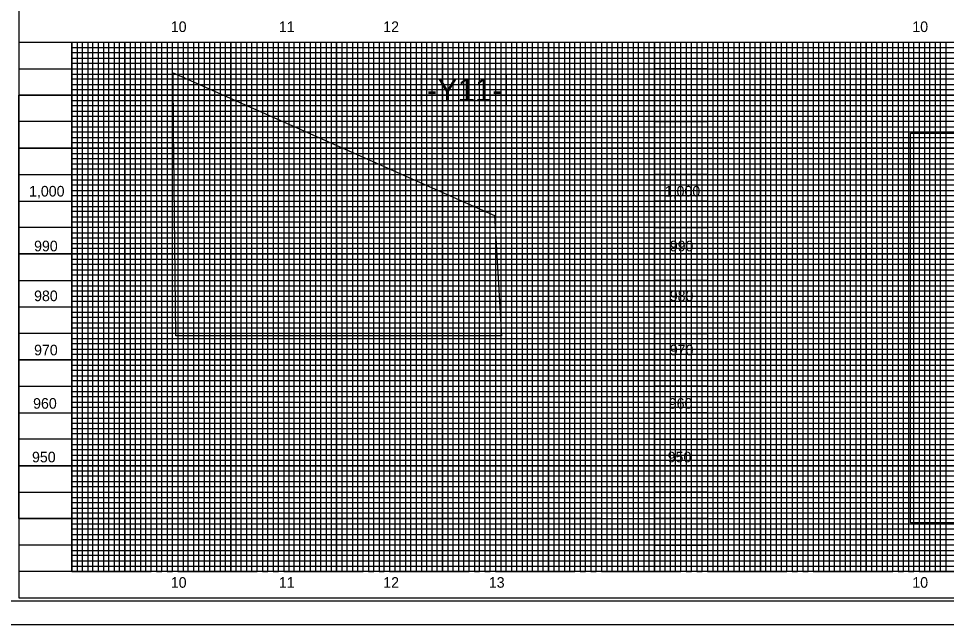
# Model space of a CAD drawing. Extents: x 1628636 to 1631253, y 896159 to 897520.
# Drawn here: x 1629226 to 1630102, y 896159 to 896731 of the extents above; entities that cross this region are included whole.
import ezdxf

# ---------------------------------------------------------------- set-up
doc = ezdxf.new("R2010")
doc.units = 0
for name, color, linetype in [('Prop DSN Text', 7, 'Continuous'), ('Prop PHM Black Shape', 7, 'Continuous'), ('Scratch_Level_6', 7, 'Continuous'), ('Sheet Cutting Line CELL', 7, 'Continuous'), ('Sheet DOT Grid CELL', 7, 'Continuous'), ('Sheet Layout Profile Border Port 2', 7, 'Continuous'), ('Sheet Plot Border Inside CELL', 7, 'Continuous'), ('Sheet Plot Border Outside CELL', 7, 'Continuous'), ('Sheet Profile CELL', 7, 'Continuous'), ('Sheet Profile Grid Major CELL', 7, 'Continuous'), ('Sheet Profile Grid Middle CELL', 7, 'Continuous'), ('Sheet Profile Grid Minor CELL', 7, 'Continuous')]:
    doc.layers.add(name, color=color, linetype=linetype)

msp = doc.modelspace()

# ---------------------------------------------------------------- linework, layer by layer
at = {"layer": 'Prop PHM Black Shape'}
for points in [[(1629826.5, 896708.9), (1629876.5, 896708.9), (1629876.5, 896683.9), (1629826.5, 896683.9)], [(1629826.5, 896683.9), (1629876.5, 896683.9), (1629876.5, 896658.9), (1629826.5, 896658.9)], [(1629606.5, 896678.9), (1629686.5, 896678.9), (1629686.5, 896648.9), (1629606.5, 896648.9)], [(1629826.5, 896658.9), (1629876.5, 896658.9), (1629876.5, 896633.9), (1629826.5, 896633.9)], [(1629826.5, 896633.9), (1629876.5, 896633.9), (1629876.5, 896608.9), (1629826.5, 896608.9)], [(1629826.5, 896608.9), (1629876.5, 896608.9), (1629876.5, 896583.9), (1629826.5, 896583.9)], [(1629826.5, 896583.9), (1629876.5, 896583.9), (1629876.5, 896558.9), (1629826.5, 896558.9)], [(1629826.5, 896558.9), (1629876.5, 896558.9), (1629876.5, 896533.9), (1629826.5, 896533.9)], [(1629826.5, 896533.9), (1629876.5, 896533.9), (1629876.5, 896508.9), (1629826.5, 896508.9)], [(1629826.5, 896508.9), (1629876.5, 896508.9), (1629876.5, 896483.9), (1629826.5, 896483.9)], [(1629826.5, 896483.9), (1629876.5, 896483.9), (1629876.5, 896458.9), (1629826.5, 896458.9)], [(1629826.5, 896458.9), (1629876.5, 896458.9), (1629876.5, 896433.9), (1629826.5, 896433.9)], [(1629826.5, 896433.9), (1629876.5, 896433.9), (1629876.5, 896408.9), (1629826.5, 896408.9)], [(1629826.5, 896408.9), (1629876.5, 896408.9), (1629876.5, 896383.9), (1629826.5, 896383.9)], [(1629826.5, 896383.9), (1629876.5, 896383.9), (1629876.5, 896358.9), (1629826.5, 896358.9)], [(1629826.5, 896358.9), (1629876.5, 896358.9), (1629876.5, 896333.9), (1629826.5, 896333.9)], [(1629826.5, 896333.9), (1629876.5, 896333.9), (1629876.5, 896308.9), (1629826.5, 896308.9)], [(1629826.5, 896308.9), (1629876.5, 896308.9), (1629876.5, 896283.9), (1629826.5, 896283.9)], [(1629826.5, 896283.9), (1629876.5, 896283.9), (1629876.5, 896258.9), (1629826.5, 896258.9)], [(1629826.5, 896258.9), (1629876.5, 896258.9), (1629876.5, 896233.9), (1629826.5, 896233.9)], [(1629826.5, 896233.9), (1629876.5, 896233.9), (1629876.5, 896208.9), (1629826.5, 896208.9)]]:
    msp.add_lwpolyline(points, close=True, dxfattribs=at)
at = {"layer": 'Scratch_Level_6'}
for points in [[(1629372.8, 896602.66), (1629372.5, 896622.96), (1629372.09, 896679.94), (1629675.45, 896545.33), (1629682.06, 896431.71), (1629374.8, 896431.63)], [(1629226.5, 896658.9), (1629776.5, 896658.9), (1629776.5, 896258.9), (1629226.5, 896258.9)], [(1630068.19, 896623), (1630370.03, 896623), (1630370.03, 896254.89), (1630068.19, 896254.89)]]:
    msp.add_lwpolyline(points, close=True, dxfattribs=at)
at = {"layer": 'Sheet Cutting Line CELL'}
msp.add_line((1629059.5, 896158.9), (1630743.5, 896158.9), dxfattribs=at)
at = {"layer": 'Sheet DOT Grid CELL'}
for p, q in [((1629226.5, 896708.9), (1630726.39, 896708.9)), ((1629276.5, 896708.9), (1629276.5, 896208.9)), ((1629326.5, 896708.9), (1629326.5, 896208.9)), ((1629376.5, 896708.9), (1629376.5, 896208.9)), ((1629426.5, 896708.9), (1629426.5, 896208.9)), ((1629476.5, 896708.9), (1629476.5, 896208.9)), ((1629526.5, 896708.9), (1629526.5, 896208.9)), ((1629576.5, 896708.9), (1629576.5, 896208.9)), ((1629626.5, 896708.9), (1629626.5, 896208.9)), ((1629676.5, 896708.9), (1629676.5, 896208.9)), ((1629726.5, 896708.9), (1629726.5, 896208.9)), ((1629776.5, 896708.9), (1629776.5, 896208.9)), ((1629826.5, 896708.9), (1629826.5, 896208.9)), ((1629876.5, 896708.9), (1629876.5, 896208.9)), ((1629926.5, 896708.9), (1629926.5, 896208.9)), ((1629976.5, 896708.9), (1629976.5, 896208.9)), ((1630026.5, 896708.9), (1630026.5, 896208.9)), ((1630076.5, 896708.9), (1630076.5, 896208.9)), ((1629226.5, 896658.9), (1630726.39, 896658.9)), ((1629226.5, 896608.9), (1630726.39, 896608.9)), ((1629226.5, 896558.9), (1630726.39, 896558.9)), ((1629226.5, 896508.9), (1630726.39, 896508.9)), ((1629226.5, 896458.9), (1630726.39, 896458.9)), ((1629226.5, 896408.9), (1630726.39, 896408.9)), ((1629226.5, 896358.9), (1630726.39, 896358.9)), ((1629226.5, 896308.9), (1630726.39, 896308.9)), ((1629226.5, 896258.9), (1630726.39, 896258.9))]:
    msp.add_line(p, q, dxfattribs=at)
at = {"layer": 'Sheet Layout Profile Border Port 2'}
msp.add_lwpolyline([(1629276.5, 896708.9), (1630676.5, 896708.9), (1630676.5, 896208.9), (1629276.5, 896208.9)], close=True, dxfattribs=at)
at = {"layer": 'Sheet Plot Border Inside CELL'}
msp.add_lwpolyline([(1629072.5, 896181.35), (1630739, 896181.35), (1630739, 897236.45), (1629072.5, 897236.45)], close=True, dxfattribs=at)
at = {"layer": 'Sheet Plot Border Outside CELL'}
msp.add_lwpolyline([(1629059.5, 896158.9), (1630743.5, 896158.9), (1630743.5, 897258.9), (1629059.5, 897258.9)], close=True, dxfattribs=at)
at = {"layer": 'Sheet Profile CELL'}
for p, q in [((1629226.5, 896708.9), (1630726.5, 896708.9)), ((1630726.5, 896208.9), (1629226.5, 896208.9)), ((1629226.5, 896183.9), (1630726.5, 896183.9)), ((1629226.5, 896183.9), (1629226.5, 896183.9)), ((1629226.5, 896183.9), (1629226.5, 896183.9)), ((1629226.5, 896183.9), (1629226.5, 896183.9)), ((1629226.5, 896183.9), (1629226.5, 896183.9)), ((1629226.5, 896183.9), (1629226.5, 896183.9)), ((1629226.5, 896183.9), (1629226.5, 896183.9)), ((1629226.5, 896183.9), (1629226.5, 896183.9))]:
    msp.add_line(p, q, dxfattribs=at)
msp.add_lwpolyline([(1630726.5, 897233.9), (1629226.5, 897233.9), (1629226.5, 896183.9), (1630726.5, 896183.9)], close=True, dxfattribs=at)
msp.add_lwpolyline([(1629264, 896183.9), (1629264, 896183.9)], dxfattribs=at)
at = {"layer": 'Sheet Profile Grid Major CELL'}
for p, q in [((1629726.5, 896708.9), (1629776.5, 896708.9)), ((1629826.5, 896708.9), (1629876.5, 896708.9)), ((1629926.5, 896708.9), (1629976.5, 896708.9)), ((1630026.5, 896708.9), (1630076.5, 896708.9)), ((1629826.5, 896683.9), (1629876.5, 896683.9)), ((1629876.5, 896658.9), (1629826.5, 896658.9)), ((1629826.5, 896633.9), (1629876.5, 896633.9)), ((1629826.5, 896608.9), (1629876.5, 896608.9)), ((1629826.5, 896583.9), (1629876.5, 896583.9)), ((1629826.5, 896558.9), (1629876.5, 896558.9)), ((1629826.5, 896533.9), (1629876.5, 896533.9)), ((1629876.5, 896508.9), (1629826.5, 896508.9)), ((1629826.5, 896483.9), (1629876.5, 896483.9)), ((1629826.5, 896458.9), (1629876.5, 896458.9)), ((1629826.5, 896433.9), (1629876.5, 896433.9)), ((1629876.5, 896408.9), (1629826.5, 896408.9)), ((1629826.5, 896383.9), (1629876.5, 896383.9)), ((1629876.5, 896358.9), (1629826.5, 896358.9)), ((1629826.5, 896333.9), (1629876.5, 896333.9)), ((1629826.5, 896308.9), (1629876.5, 896308.9)), ((1629826.5, 896283.9), (1629876.5, 896283.9)), ((1629826.5, 896258.9), (1629876.5, 896258.9)), ((1629826.5, 896233.9), (1629876.5, 896233.9)), ((1629226.5, 896208.9), (1629226.5, 896208.9))]:
    msp.add_line(p, q, dxfattribs=at)
for points in [[(1629276.5, 896708.9), (1629276.5, 896208.9), (1629326.5, 896208.9), (1629326.5, 896708.9), (1629376.5, 896708.9), (1629376.5, 896208.9), (1629426.5, 896208.9), (1629426.5, 896708.9), (1629476.5, 896708.9), (1629476.5, 896208.9), (1629526.5, 896208.9), (1629526.5, 896708.9), (1629576.5, 896708.9), (1629576.5, 896208.9), (1629626.5, 896208.9), (1629626.5, 896708.9), (1629676.5, 896708.9), (1629676.5, 896208.9), (1629726.5, 896208.9), (1629726.5, 896708.9), (1629776.5, 896708.9), (1629776.5, 896208.9), (1629826.5, 896208.9), (1629826.5, 896708.9), (1629876.5, 896708.9), (1629876.5, 896208.9), (1629926.5, 896208.9), (1629926.5, 896708.9), (1629976.5, 896708.9), (1629976.5, 896208.9), (1630026.5, 896208.9), (1630026.5, 896708.9), (1630076.5, 896708.9), (1630076.5, 896208.9), (1630126.5, 896208.9)], [(1630726.5, 896658.9), (1629226.5, 896658.9)], [(1630726.5, 896608.9), (1629226.5, 896608.9), (1629226.5, 896558.9), (1630726.5, 896558.9)], [(1630726.5, 896508.9), (1629226.5, 896508.9), (1629226.5, 896458.9), (1630726.5, 896458.9)], [(1630726.5, 896408.9), (1629226.5, 896408.9), (1629226.5, 896358.9), (1630726.5, 896358.9)], [(1630726.5, 896308.9), (1629226.5, 896308.9), (1629226.5, 896308.9), (1629226.5, 896258.9), (1630726.5, 896258.9)], [(1630726.5, 896208.9), (1629226.5, 896208.9)]]:
    msp.add_lwpolyline(points, dxfattribs=at)
at = {"layer": 'Sheet Profile Grid Middle CELL'}
for points in [[(1629251.5, 896708.9), (1629301.5, 896708.9), (1629301.5, 896208.9), (1629351.5, 896208.9), (1629351.5, 896708.9), (1629401.5, 896708.9), (1629401.5, 896208.9), (1629451.5, 896208.9), (1629451.5, 896708.9), (1629501.5, 896708.9), (1629501.5, 896208.9), (1629551.5, 896208.9), (1629551.5, 896708.9), (1629601.5, 896708.9), (1629601.5, 896208.9), (1629651.5, 896208.9), (1629651.5, 896708.9), (1629701.5, 896708.9), (1629701.5, 896208.9), (1629751.5, 896208.9), (1629751.5, 896708.9), (1629801.5, 896708.9), (1629801.5, 896208.9), (1629851.5, 896208.9), (1629851.5, 896208.9), (1629851.5, 896708.9), (1629901.5, 896708.9), (1629901.5, 896208.9), (1629951.5, 896208.9), (1629951.5, 896708.9), (1630001.5, 896708.9), (1630001.5, 896208.9), (1630051.5, 896208.9), (1630051.5, 896708.9), (1630101.5, 896708.9), (1630101.5, 896208.9), (1630151.5, 896208.9)], [(1629226.5, 896683.9), (1630726.5, 896683.9)], [(1630726.5, 896633.9), (1629226.5, 896633.9), (1629226.5, 896583.9), (1630726.5, 896583.9)], [(1630726.5, 896533.9), (1629226.5, 896533.9), (1629226.5, 896483.9), (1630726.5, 896483.9)], [(1630726.5, 896433.9), (1629226.5, 896433.9), (1629226.5, 896383.9), (1630726.5, 896383.9)], [(1630726.5, 896333.9), (1629226.5, 896333.9), (1629226.5, 896283.9), (1630726.5, 896283.9)], [(1630726.5, 896233.9), (1629226.5, 896233.9)]]:
    msp.add_lwpolyline(points, dxfattribs=at)
at = {"layer": 'Sheet Profile Grid Minor CELL'}
for p, q in [((1629276.5, 896703.9), (1630676.5, 896703.9)), ((1630676.5, 896698.9), (1629276.5, 896698.9)), ((1629276.5, 896693.9), (1630676.5, 896693.9)), ((1630676.5, 896688.9), (1629276.5, 896688.9)), ((1629276.5, 896678.9), (1630676.5, 896678.9)), ((1630676.5, 896673.9), (1629276.5, 896673.9)), ((1629276.5, 896668.9), (1630676.5, 896668.9)), ((1630676.5, 896663.9), (1629276.5, 896663.9)), ((1629276.5, 896653.9), (1630676.5, 896653.9)), ((1630676.5, 896648.9), (1629276.5, 896648.9)), ((1629276.5, 896643.9), (1630676.5, 896643.9)), ((1630676.5, 896638.9), (1629276.5, 896638.9)), ((1629276.5, 896628.9), (1630676.5, 896628.9)), ((1630676.5, 896623.9), (1629276.5, 896623.9)), ((1629276.5, 896618.9), (1630676.5, 896618.9)), ((1630676.5, 896613.9), (1629276.5, 896613.9)), ((1629276.5, 896603.9), (1630676.5, 896603.9)), ((1630676.5, 896598.9), (1629276.5, 896598.9)), ((1629276.5, 896593.9), (1630676.5, 896593.9)), ((1630676.5, 896588.9), (1629276.5, 896588.9)), ((1629276.5, 896578.9), (1630676.5, 896578.9)), ((1630676.5, 896573.9), (1629276.5, 896573.9)), ((1629276.5, 896568.9), (1630676.5, 896568.9)), ((1630676.5, 896563.9), (1629276.5, 896563.9)), ((1629276.5, 896553.9), (1630676.5, 896553.9)), ((1630676.5, 896548.9), (1629276.5, 896548.9)), ((1629276.5, 896543.9), (1630676.5, 896543.9)), ((1630676.5, 896538.9), (1629276.5, 896538.9)), ((1629276.5, 896528.9), (1630676.5, 896528.9)), ((1630676.5, 896523.9), (1629276.5, 896523.9)), ((1629276.5, 896518.9), (1630676.5, 896518.9)), ((1630676.5, 896513.9), (1629276.5, 896514.05)), ((1629276.5, 896503.9), (1630676.5, 896503.9)), ((1630676.5, 896498.9), (1629276.5, 896498.9)), ((1629276.5, 896493.9), (1630676.5, 896493.9)), ((1630676.5, 896488.9), (1629276.5, 896488.9)), ((1629276.5, 896478.9), (1630676.5, 896478.9)), ((1630676.5, 896473.9), (1629276.5, 896473.9)), ((1629276.5, 896468.9), (1630676.5, 896468.9)), ((1630676.5, 896463.9), (1629276.5, 896463.9)), ((1629276.5, 896453.9), (1630676.5, 896453.9)), ((1630676.5, 896448.9), (1629276.5, 896448.9)), ((1629276.5, 896443.9), (1630676.5, 896443.9)), ((1630676.5, 896438.9), (1629276.5, 896438.9)), ((1629276.5, 896428.9), (1630676.5, 896428.9)), ((1630676.5, 896423.9), (1629276.5, 896423.9)), ((1629276.5, 896418.9), (1630676.5, 896418.9)), ((1630676.5, 896413.9), (1629276.5, 896413.9)), ((1629276.5, 896403.9), (1630676.5, 896403.9)), ((1630676.5, 896398.9), (1629276.5, 896398.9)), ((1629276.5, 896393.9), (1630676.5, 896393.9)), ((1630676.5, 896388.9), (1629276.5, 896388.9)), ((1629276.5, 896378.9), (1630676.5, 896378.9)), ((1630676.5, 896373.9), (1629276.5, 896373.9)), ((1629276.5, 896368.9), (1630676.5, 896368.9)), ((1630676.5, 896363.9), (1629276.5, 896363.9)), ((1629276.5, 896353.9), (1630676.5, 896353.9)), ((1630676.5, 896348.9), (1629276.5, 896348.9)), ((1629276.5, 896343.9), (1630676.5, 896343.9)), ((1630676.5, 896338.9), (1629276.5, 896338.9)), ((1629276.5, 896328.9), (1630676.5, 896328.9)), ((1630676.5, 896323.9), (1629276.5, 896323.9)), ((1629276.5, 896318.9), (1630676.5, 896318.9)), ((1630676.5, 896313.9), (1629276.5, 896313.9)), ((1629276.5, 896303.9), (1630676.5, 896303.9)), ((1630676.5, 896298.9), (1629276.5, 896298.9)), ((1629276.5, 896293.9), (1630676.5, 896293.9)), ((1630676.5, 896288.9), (1629276.5, 896288.9)), ((1629276.5, 896278.9), (1630676.5, 896278.9)), ((1630676.5, 896273.9), (1629276.5, 896273.9)), ((1629276.5, 896268.9), (1630676.5, 896268.9)), ((1630676.5, 896263.9), (1629276.5, 896263.9)), ((1629276.5, 896253.9), (1630676.5, 896253.9)), ((1630676.5, 896248.9), (1629276.5, 896248.9)), ((1629276.5, 896243.9), (1630676.5, 896243.9)), ((1630676.5, 896238.9), (1629276.5, 896238.9)), ((1629276.5, 896228.9), (1630676.5, 896228.9)), ((1630676.5, 896223.9), (1629276.5, 896223.9)), ((1629276.5, 896218.9), (1630676.5, 896218.9)), ((1629276.5, 896213.9), (1630676.5, 896213.9))]:
    msp.add_line(p, q, dxfattribs=at)
for points in [[(1629276.5, 896708.9), (1629281.5, 896708.9), (1629281.5, 896208.9), (1629286.5, 896208.9), (1629286.5, 896708.9), (1629291.5, 896708.9), (1629291.5, 896208.9), (1629296.5, 896208.9), (1629296.5, 896708.9), (1629306.5, 896708.9), (1629306.5, 896208.9), (1629311.5, 896208.9), (1629311.5, 896708.9), (1629316.5, 896708.9), (1629316.5, 896208.9), (1629321.5, 896208.9), (1629331.5, 896208.9), (1629336.5, 896208.9), (1629336.5, 896708.9), (1629341.5, 896708.9), (1629341.5, 896208.9), (1629346.5, 896208.9), (1629346.5, 896708.9), (1629356.5, 896708.9), (1629356.5, 896208.9), (1629361.5, 896208.9), (1629361.5, 896708.9), (1629366.5, 896708.9), (1629366.5, 896208.9), (1629371.5, 896208.9), (1629371.5, 896708.9), (1629381.5, 896708.9), (1629381.5, 896208.9), (1629386.5, 896208.9), (1629386.5, 896708.9), (1629391.5, 896708.9), (1629391.5, 896208.9), (1629396.5, 896208.9), (1629396.5, 896708.9), (1629406.5, 896708.9), (1629406.5, 896208.9), (1629411.5, 896208.9), (1629411.5, 896708.9), (1629416.5, 896708.9), (1629416.5, 896208.9), (1629421.5, 896208.9), (1629421.5, 896708.9), (1629431.5, 896708.9), (1629431.5, 896208.9), (1629436.5, 896208.9), (1629436.5, 896708.9), (1629441.5, 896708.9), (1629441.5, 896208.9), (1629446.5, 896208.9), (1629446.5, 896708.9), (1629456.5, 896708.9), (1629456.5, 896208.9), (1629461.5, 896208.9), (1629461.5, 896708.9), (1629466.5, 896708.9), (1629466.5, 896208.9), (1629471.5, 896208.9), (1629471.5, 896708.9), (1629481.5, 896708.9), (1629481.5, 896208.9), (1629486.5, 896208.9), (1629486.5, 896708.9), (1629491.5, 896708.9), (1629491.5, 896208.9)], [(1629321.5, 896208.9), (1629321.5, 896708.9), (1629331.5, 896708.9), (1629331.5, 896208.9)], [(1629491.5, 896208.9), (1629496.5, 896208.9), (1629496.5, 896708.9), (1629506.5, 896708.9), (1629506.5, 896208.9), (1629511.5, 896208.9), (1629511.5, 896708.9), (1629516.5, 896708.9), (1629516.5, 896208.9), (1629521.5, 896208.9), (1629521.5, 896708.9), (1629531.5, 896708.9), (1629531.5, 896208.9), (1629536.5, 896208.9), (1629536.5, 896708.9), (1629541.5, 896708.9), (1629541.5, 896208.9), (1629546.5, 896208.9), (1629546.5, 896708.9), (1629556.5, 896708.9), (1629556.5, 896208.9), (1629561.5, 896208.9), (1629561.5, 896708.9), (1629566.5, 896708.9), (1629566.5, 896208.9), (1629571.5, 896208.9), (1629571.5, 896708.9), (1629581.5, 896708.9), (1629581.5, 896208.9), (1629586.5, 896208.9), (1629586.5, 896708.9), (1629591.5, 896708.9), (1629591.5, 896208.9), (1629596.5, 896208.9), (1629596.5, 896708.9), (1629606.5, 896708.9), (1629606.5, 896208.9), (1629611.5, 896208.9), (1629611.5, 896708.9), (1629616.5, 896708.9), (1629616.5, 896208.9), (1629621.5, 896208.9), (1629621.5, 896708.9), (1629631.5, 896708.9), (1629631.5, 896208.9), (1629636.5, 896208.9), (1629636.5, 896708.9), (1629641.5, 896708.9), (1629641.5, 896208.9), (1629646.5, 896208.9), (1629646.5, 896708.9), (1629656.5, 896708.9), (1629656.5, 896208.9), (1629661.5, 896208.9), (1629661.5, 896708.9), (1629666.5, 896708.9), (1629666.5, 896208.9), (1629671.5, 896208.9), (1629671.5, 896708.9), (1629681.5, 896708.9), (1629681.5, 896208.9), (1629686.5, 896208.9), (1629686.5, 896708.9), (1629691.5, 896708.9), (1629691.5, 896208.9), (1629696.5, 896208.9), (1629696.5, 896708.9), (1629706.5, 896708.9), (1629706.5, 896208.9), (1629711.5, 896208.9), (1629711.5, 896708.9), (1629716.5, 896708.9), (1629716.5, 896208.9), (1629721.5, 896208.9), (1629721.5, 896708.9), (1629731.5, 896708.9), (1629731.5, 896208.9), (1629736.5, 896208.9), (1629736.5, 896708.9), (1629741.5, 896708.9), (1629741.5, 896208.9), (1629746.5, 896208.9), (1629746.5, 896708.9), (1629756.5, 896708.9), (1629756.5, 896208.9), (1629761.5, 896208.9), (1629761.5, 896708.9), (1629766.5, 896708.9), (1629766.5, 896208.9), (1629771.5, 896208.9), (1629771.5, 896708.9), (1629781.5, 896708.9), (1629781.5, 896208.9), (1629786.5, 896208.9), (1629786.5, 896708.9), (1629791.5, 896708.9), (1629791.5, 896208.9), (1629796.5, 896208.9), (1629796.5, 896708.9), (1629806.5, 896708.9)], [(1629806.5, 896708.9), (1629806.5, 896208.9), (1629811.5, 896208.9), (1629811.5, 896708.9), (1629816.5, 896708.9), (1629816.5, 896208.9), (1629821.5, 896208.9), (1629821.5, 896708.9), (1629831.5, 896708.9), (1629831.5, 896208.9), (1629836.5, 896208.9), (1629836.5, 896708.9), (1629841.5, 896708.9), (1629841.5, 896208.9), (1629846.5, 896208.9), (1629846.5, 896708.9), (1629856.5, 896708.9), (1629856.5, 896208.9), (1629861.5, 896208.9), (1629861.5, 896708.9), (1629866.5, 896708.9), (1629866.5, 896208.9), (1629871.5, 896208.9), (1629871.5, 896708.9), (1629881.5, 896708.9), (1629881.5, 896208.9), (1629886.5, 896208.9), (1629886.5, 896708.9), (1629891.5, 896708.9), (1629891.5, 896208.9), (1629896.5, 896208.9), (1629896.5, 896708.9), (1629906.5, 896708.9), (1629906.5, 896208.9), (1629911.5, 896208.9), (1629911.5, 896708.9), (1629916.5, 896708.9), (1629916.5, 896208.9), (1629921.5, 896208.9), (1629921.5, 896708.9), (1629931.5, 896708.9), (1629931.5, 896208.9), (1629931.5, 896208.9), (1629936.5, 896208.9), (1629936.5, 896708.9), (1629941.5, 896708.9), (1629941.5, 896208.9), (1629946.5, 896208.9), (1629946.5, 896708.9), (1629956.5, 896708.9), (1629956.5, 896208.9), (1629961.5, 896208.9), (1629961.5, 896708.9), (1629966.5, 896708.9), (1629966.5, 896208.9), (1629971.5, 896208.9), (1629971.5, 896708.9), (1629981.5, 896708.9), (1629981.5, 896208.9), (1629986.5, 896208.9), (1629986.5, 896708.9), (1629991.5, 896708.9), (1629991.5, 896208.9), (1629996.5, 896208.9), (1629996.5, 896708.9), (1630006.5, 896708.9), (1630006.5, 896208.9), (1630011.5, 896208.9), (1630011.5, 896708.9), (1630016.5, 896708.9), (1630016.5, 896208.9), (1630021.5, 896208.9), (1630021.5, 896708.9), (1630031.5, 896708.9), (1630031.5, 896208.9), (1630036.5, 896208.9), (1630036.5, 896708.9), (1630041.5, 896708.9), (1630041.5, 896208.9), (1630046.5, 896208.9), (1630046.5, 896708.9), (1630056.5, 896708.9), (1630056.5, 896208.9), (1630061.5, 896208.9), (1630061.5, 896708.9), (1630066.5, 896708.9), (1630066.5, 896208.9), (1630071.5, 896208.9), (1630071.5, 896708.9), (1630081.5, 896708.9), (1630081.5, 896208.9), (1630086.2, 896209.45), (1630086.5, 896208.9), (1630086.5, 896708.9), (1630091.5, 896708.9), (1630091.5, 896208.9), (1630096.5, 896208.9), (1630096.5, 896708.9), (1630106.5, 896708.9)]]:
    msp.add_lwpolyline(points, dxfattribs=at)

# ---------------------------------------------------------------- texts
at = {"layer": 'Prop DSN Text'}
for s, height, p in [('10', 10, (1629369.96, 896718.58)), ('11', 10, (1629471.94, 896718.58)), ('12', 10, (1629570.51, 896718.58)), ('10', 10, (1630069.96, 896718.58)), ('-Y11-', 21.875, (1629611.63, 896652.96)), ('1,000', 10, (1629236.15, 896563.17)), ('1,000', 10, (1629836.25, 896563.17)), ('990', 10, (1629240.89, 896511.41)), ('990', 10, (1629840.99, 896511.41)), ('980', 10, (1629240.89, 896464.33)), ('980', 10, (1629840.99, 896464.33)), ('970', 10, (1629240.89, 896413.14)), ('970', 10, (1629840.99, 896413.14)), ('960', 10, (1629239.97, 896362.72)), ('960', 10, (1629840.07, 896362.72)), ('950', 10, (1629238.93, 896312.05)), ('950', 10, (1629839.03, 896312.05)), ('10', 10, (1629369.96, 896193.58)), ('11', 10, (1629471.94, 896193.58)), ('12', 10, (1629570.51, 896193.58)), ('13', 10, (1629670.18, 896193.58)), ('10', 10, (1630069.96, 896193.58))]:
    msp.add_text(s, height=height, dxfattribs=at).set_placement(p)

doc.saveas('drawing.dxf')
